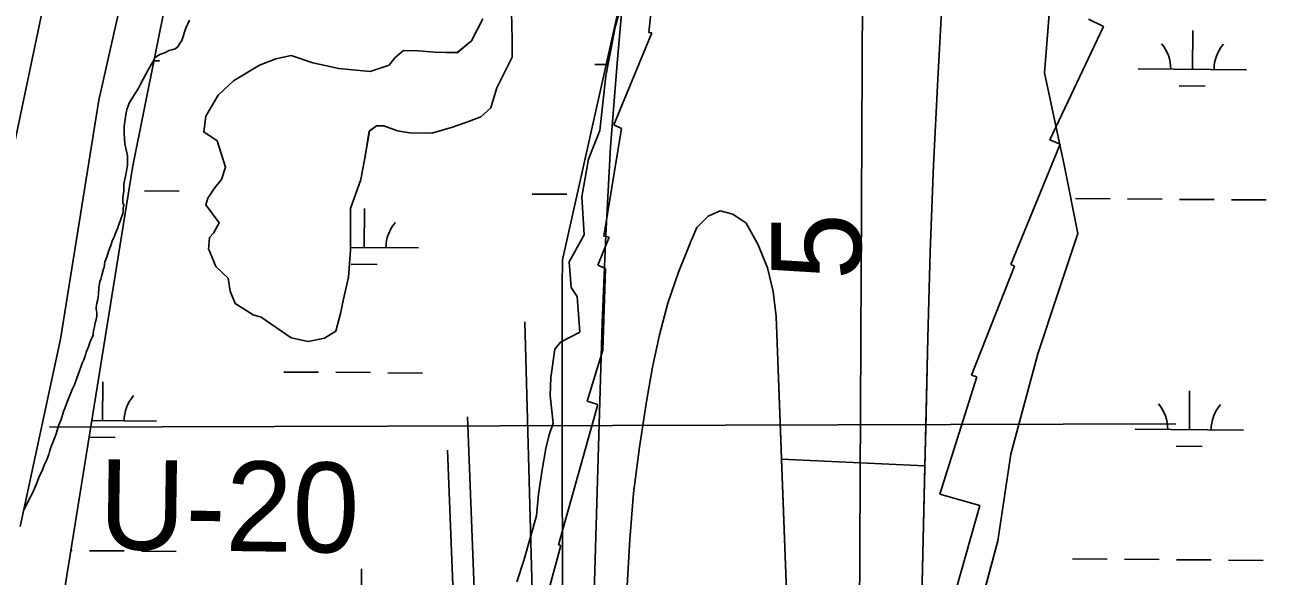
# Model space of a CAD drawing. Extents: x 3271442 to 3309282, y 752266 to 777610.
# Drawn here: x 3284369 to 3285515, y 760687 to 761196 of the extents above; entities that cross this region are included whole.
import ezdxf

# ---------------------------------------------------------------- set-up
doc = ezdxf.new("R2010")
doc.units = 0
for name, color, linetype in [('V-LEVE-TOET', 7, 'Continuous'), ('V-RIVR-RANG', 7, 'Continuous'), ('V-RIVR-RANG-IDEN', 7, 'Continuous'), ('V-RRAP-RVMT', 7, 'Continuous'), ('V-SITE-VEGE', 7, 'Continuous'), ('V-SURV-LINE', 7, 'Continuous'), ('V-TOPO-DPTH', 7, 'Continuous'), ('V-TOPO-MAJR', 7, 'Continuous'), ('V-TOPO-MINR', 7, 'Continuous'), ('V-TOPO-MINR-IDEN', 7, 'Continuous'), ('V-TOPO-SHOR', 7, 'Continuous'), ('V-TOPO-WATR', 7, 'Continuous'), ('V-WETL-SWMP', 7, 'Continuous')]:
    doc.layers.add(name, color=color, linetype=linetype)

msp = doc.modelspace()

# ---------------------------------------------------------------- linework, layer by layer
at = {"layer": 'V-LEVE-TOET'}
msp.add_lwpolyline([(3284364.4, 760732.6), (3284401.6, 760905.6), (3284437.2, 761126.1), (3284466.3, 761256), (3284536.5, 761573.6), (3284580.9, 761825.5), (3284684.3, 762338.7), (3284774.1, 762796.9), (3284845.7, 763187.2), (3284909.2, 763499.9), (3284968.8, 763777.1), (3284994.4, 763906.7), (3284995.4, 763964), (3285002.6, 764015), (3285013.5, 764062), (3285019.1, 764089.2)], dxfattribs=at)
at = {"layer": 'V-RIVR-RANG'}
msp.add_line((3284391.5, 760824.3), (3285431.5, 760827.4), dxfattribs=at)
at = {"layer": 'V-RRAP-RVMT'}
for p, q in [((3284945, 761188.5), (3284948.1, 761217.6)), ((3285364.8, 761194.1), (3285315.2, 761089.4)), ((3285350.9, 761200.9), (3285364.8, 761194.1)), ((3284912.7, 761103.4), (3284947.7, 761188.3)), ((3284947.7, 761188.3), (3284945, 761188.5)), ((3284903.4, 761000.5), (3284919.7, 761100)), ((3284919.7, 761100), (3284912.7, 761103.4)), ((3285315.2, 761089.4), (3285324.9, 761085.4)), ((3285324.9, 761085.4), (3285279.2, 760974.4)), ((3284897.9, 760973.7), (3284908.2, 760999.7)), ((3284908.2, 760999.7), (3284903.4, 761000.5)), ((3284905.1, 760970.9), (3284897.9, 760973.7)), ((3285282.7, 760973), (3285243, 760872.4)), ((3285279.2, 760974.4), (3285282.7, 760973)), ((3284902.6, 760895.5), (3284905.1, 760970.9)), ((3284887.9, 760848.3), (3284902.6, 760895.5)), ((3285248, 760870.8), (3285213.7, 760762.3)), ((3285243, 760872.4), (3285248, 760870.8)), ((3284897.8, 760845.1), (3284887.9, 760848.3)), ((3284861.4, 760715.6), (3284897.8, 760845.1)), ((3285213.7, 760762.3), (3285250.5, 760751.9)), ((3285250.5, 760751.9), (3285217, 760633.1)), ((3284844.3, 760643), (3284863.7, 760715)), ((3284863.7, 760715), (3284861.4, 760715.6))]:
    msp.add_line(p, q, dxfattribs=at)
at = {"layer": 'V-SITE-VEGE'}
for p, q in [((3284818.8, 761182.6), (3284818.1, 761207.2)), ((3284917.3, 761205.6), (3284914, 761193.4)), ((3284513.6, 761181.1), (3284517.3, 761192.5)), ((3284517.3, 761192.5), (3284520.9, 761200.1)), ((3284791.7, 761201.1), (3284781.3, 761180.9)), ((3284914, 761193.4), (3284905.3, 761148.7)), ((3284511.4, 761178.2), (3284513.6, 761181.1)), ((3284781.3, 761180.9), (3284768, 761170)), ((3284818.7, 761165.7), (3284818.8, 761182.6)), ((3284488.9, 761165.4), (3284493.4, 761168.3)), ((3284493.4, 761168.3), (3284498.5, 761170.2)), ((3284498.5, 761170.2), (3284501.8, 761172)), ((3284501.8, 761172), (3284504.4, 761172.7)), ((3284504.4, 761172.7), (3284507.7, 761173.4)), ((3284507.7, 761173.4), (3284509.9, 761175.3)), ((3284509.9, 761175.3), (3284511.4, 761178.2)), ((3284718.4, 761172), (3284710.3, 761165.1)), ((3284732, 761171.6), (3284718.4, 761172)), ((3284747.1, 761170.4), (3284732, 761171.6)), ((3284768, 761170), (3284747.1, 761170.4)), ((3284482.6, 761154.1), (3284487.7, 761163.2)), ((3284487.7, 761163.2), (3284488.9, 761165.4)), ((3284585.3, 761158.6), (3284561.4, 761144)), ((3284600.4, 761164.4), (3284585.3, 761158.6)), ((3284614.8, 761167.3), (3284600.4, 761164.4)), ((3284634.6, 761160.6), (3284614.8, 761167.3)), ((3284658.8, 761155.4), (3284634.6, 761160.6)), ((3284705.1, 761158.5), (3284687.5, 761152.7)), ((3284710.3, 761165.1), (3284705.1, 761158.5)), ((3284804.6, 761137.5), (3284818.7, 761165.7)), ((3284475.6, 761140.9), (3284482.6, 761154.1)), ((3284687.5, 761152.7), (3284658.8, 761155.4)), ((3284905.3, 761148.7), (3284899.6, 761098)), ((3284470, 761131.3), (3284473.4, 761136.5)), ((3284473.4, 761136.5), (3284475.6, 761140.9)), ((3284561.4, 761144), (3284547.4, 761130.9)), ((3284802.4, 761130.5), (3284804.6, 761137.5)), ((3284463, 761117.4), (3284465.2, 761123.3)), ((3284465.2, 761123.3), (3284470, 761131.3)), ((3284547.4, 761130.9), (3284535.9, 761111.5)), ((3284799, 761119.1), (3284802.4, 761130.5)), ((3284460.4, 761102), (3284462.2, 761114.5)), ((3284462.2, 761114.5), (3284463, 761117.4)), ((3284535.9, 761111.5), (3284534, 761096.8)), ((3284779.5, 761106.7), (3284789.8, 761110.7)), ((3284789.8, 761110.7), (3284799, 761119.1)), ((3284460.3, 761095.4), (3284460.4, 761102)), ((3284686.8, 761097.6), (3284693.5, 761102.3)), ((3284693.5, 761102.3), (3284700.1, 761102.6)), ((3284700.1, 761102.6), (3284712.9, 761097.8)), ((3284744.5, 761095.8), (3284763.7, 761101.3)), ((3284763.7, 761101.3), (3284779.5, 761106.7)), ((3284461, 761085.8), (3284460.3, 761095.4)), ((3284534, 761096.8), (3284546.4, 761088.6)), ((3284546.4, 761088.6), (3284554.1, 761064.3)), ((3284682.7, 761072.6), (3284686.8, 761097.6)), ((3284712.9, 761097.8), (3284724, 761095.9)), ((3284724, 761095.9), (3284744.5, 761095.8)), ((3284899.6, 761098), (3284889.2, 761071.6)), ((3284462.5, 761079.2), (3284461, 761085.8)), ((3284463.5, 761074.8), (3284462.5, 761079.2)), ((3284462.7, 761060.5), (3284463.5, 761066)), ((3284463.5, 761066), (3284463.5, 761074.8)), ((3284678.9, 761052.8), (3284682.7, 761072.6)), ((3284889.2, 761071.6), (3284883.2, 761037)), ((3284460.1, 761048.7), (3284462.7, 761060.5)), ((3284554.1, 761064.3), (3284550.3, 761053)), ((3284459.3, 761035.9), (3284460.1, 761042.5)), ((3284460.1, 761042.5), (3284460.1, 761048.7)), ((3284544, 761044.9), (3284537.8, 761035.8)), ((3284550.3, 761053), (3284544, 761044.9)), ((3284669.6, 761026), (3284678.9, 761052.8)), ((3284459.3, 761031.4), (3284459.3, 761035.9)), ((3284459.5, 761030.9), (3284459.3, 761031.4)), ((3284460, 761029.2), (3284459.5, 761030.9)), ((3284537.8, 761035.8), (3284535.9, 761029.5)), ((3284883.2, 761037), (3284885.2, 761001.8)), ((3284457.5, 761016.3), (3284458.3, 761019.2)), ((3284458.3, 761019.2), (3284459.2, 761021.3)), ((3284459.2, 761021.3), (3284459.6, 761024.2)), ((3284459.6, 761026.3), (3284460, 761029.2)), ((3284459.6, 761024.2), (3284459.6, 761026.3)), ((3284535.9, 761029.5), (3284548.3, 761012.9)), ((3284669.5, 760987.8), (3284669.6, 761026)), ((3284452.4, 761003.3), (3284454.5, 761008.3)), ((3284454.5, 761008.3), (3284455, 761009.8)), ((3284455, 761009.8), (3284455.4, 761011.2)), ((3284455.4, 761011.2), (3284457.5, 761016.3)), ((3284548.3, 761012.9), (3284542.8, 761003.4)), ((3284448.2, 760992), (3284449.5, 760996.1)), ((3284449.5, 760996.1), (3284450.3, 760998.2)), ((3284450.3, 760998.2), (3284451.6, 761000.7)), ((3284451.6, 761000.7), (3284452.4, 761003.3)), ((3284539.4, 760999.4), (3284538.3, 760988.3)), ((3284542.8, 761003.4), (3284539.4, 760999.4)), ((3284885.2, 761001.8), (3284871.5, 760976.8)), ((3284444.4, 760981.1), (3284446.1, 760986.5)), ((3284446.1, 760986.5), (3284447, 760989)), ((3284447, 760989), (3284448.2, 760992)), ((3284538.3, 760988.3), (3284539, 760987.6)), ((3284539, 760987.6), (3284545.2, 760972.5)), ((3284667.5, 760962.8), (3284669.5, 760987.8)), ((3284441.9, 760971.8), (3284442.7, 760976.9)), ((3284442.7, 760976.9), (3284444.4, 760981.1)), ((3284871.5, 760976.8), (3284873.2, 760953.3)), ((3284438.9, 760960.9), (3284439.8, 760964.7)), ((3284439.8, 760964.7), (3284441.5, 760970.5)), ((3284441.5, 760970.5), (3284441.9, 760971.8)), ((3284545.2, 760972.5), (3284556.5, 760961.8)), ((3284556.5, 760961.8), (3284558.3, 760949.7)), ((3284662.6, 760941.1), (3284667.5, 760962.8)), ((3284436.8, 760947.1), (3284437.2, 760953)), ((3284437.2, 760953), (3284438.1, 760958.9)), ((3284438.1, 760958.9), (3284438.9, 760960.9)), ((3284873.2, 760953.3), (3284878.7, 760944.8)), ((3284434.7, 760935), (3284435.1, 760938.7)), ((3284435.1, 760938.7), (3284436, 760942.1)), ((3284436, 760942.1), (3284436.8, 760947.1)), ((3284558.3, 760949.7), (3284563, 760938.3)), ((3284660.4, 760930.5), (3284662.6, 760941.1)), ((3284878.7, 760944.8), (3284881.1, 760912.1)), ((3284434.7, 760932.9), (3284434.7, 760935)), ((3284435.1, 760930.4), (3284434.7, 760932.9)), ((3284435.1, 760926.6), (3284435.1, 760930.4)), ((3284563, 760938.3), (3284579.5, 760927.9)), ((3284579.5, 760927.9), (3284586.9, 760925.7)), ((3284655.9, 760912.9), (3284660.4, 760930.5)), ((3284432.1, 760913.2), (3284433, 760916.9)), ((3284433, 760916.9), (3284433.8, 760920.7)), ((3284433.8, 760920.7), (3284434.7, 760923.6)), ((3284434.7, 760923.6), (3284435.1, 760926.6)), ((3284586.9, 760925.7), (3284614.7, 760906.8)), ((3284428.8, 760902.3), (3284430.5, 760906.9)), ((3284430.5, 760906.9), (3284431.7, 760909)), ((3284431.7, 760910.7), (3284432.1, 760913.2)), ((3284431.7, 760909), (3284431.7, 760910.7)), ((3284614.7, 760906.8), (3284630.5, 760903.4)), ((3284630.5, 760903.4), (3284645.6, 760906.3)), ((3284645.6, 760906.3), (3284655.9, 760912.9)), ((3284881.1, 760912.1), (3284863.4, 760902.6)), ((3284424.6, 760891), (3284425.4, 760893.5)), ((3284425.4, 760893.5), (3284427.5, 760898.5)), ((3284427.5, 760898.5), (3284428.8, 760902.3)), ((3284858.3, 760896.4), (3284854.5, 760870)), ((3284863.4, 760902.6), (3284858.3, 760896.4)), ((3284420.8, 760880.5), (3284421.6, 760883.4)), ((3284421.6, 760883.4), (3284423.3, 760886.4)), ((3284423.3, 760886.4), (3284424.6, 760891)), ((3284414.5, 760863.3), (3284416.6, 760869.6)), ((3284416.6, 760869.6), (3284419.1, 760876.3)), ((3284419.1, 760876.3), (3284420.8, 760880.5)), ((3284854.5, 760870), (3284853.7, 760853.5)), ((3284408.1, 760848.2), (3284412.3, 760859.1)), ((3284412.3, 760859.1), (3284414.5, 760863.3)), ((3284406, 760842.4), (3284408.1, 760848.2)), ((3284853.7, 760853.5), (3284856.5, 760828.1)), ((3284402.2, 760831.5), (3284404.4, 760838.6)), ((3284404.4, 760838.6), (3284406, 760842.4)), ((3284397.6, 760818.1), (3284400.1, 760826.5)), ((3284400.1, 760826.5), (3284402.2, 760831.5)), ((3284856.5, 760828.1), (3284852.8, 760817.1)), ((3284395.1, 760811.8), (3284397.6, 760818.1)), ((3284852.8, 760817.1), (3284849.8, 760804.6)), ((3284390.9, 760799.2), (3284391.7, 760802.6)), ((3284391.7, 760802.6), (3284393, 760806.3)), ((3284393, 760806.3), (3284395.1, 760811.8)), ((3284849.8, 760804.6), (3284846.4, 760784.8)), ((3284386.7, 760789.2), (3284388.8, 760793.4)), ((3284388.8, 760793.4), (3284390.9, 760799.2)), ((3284381.6, 760777.9), (3284385, 760785)), ((3284385, 760785), (3284386.7, 760789.2)), ((3284846.4, 760784.8), (3284843, 760762.4)), ((3284375.7, 760763.2), (3284379.5, 760772)), ((3284379.5, 760772), (3284381.6, 760777.9)), ((3284367.7, 760747.7), (3284372.3, 760757.3)), ((3284372.3, 760757.3), (3284375.7, 760763.2)), ((3284843, 760762.4), (3284841.1, 760742.5)), ((3284841.1, 760742.5), (3284829.5, 760701.1)), ((3284829.5, 760701.1), (3284823.1, 760681.6))]:
    msp.add_line(p, q, dxfattribs=at)
msp.add_lwpolyline([(3285242.4, 760626.6), (3285267.1, 760719.2), (3285279.4, 760799.5), (3285304.1, 760892), (3285322.6, 760947.6), (3285341.1, 761003.2), (3285328.8, 761064.9), (3285310.2, 761151.3), (3285317.4, 761240.3)], dxfattribs=at)
at = {"layer": 'V-SURV-LINE'}
msp.add_lwpolyline([(3284456.7, 761551.7), (3284311.1, 760858.6)], dxfattribs=at)
at = {"layer": 'V-TOPO-DPTH'}
for points in [[(3285248.1, 762689.8), (3284865.2, 760978.9)], [(3285066.9, 760812.8), (3285067.6, 760794.8), (3285199.9, 760788.7), (3285200.7, 760823), (3285202.6, 760906.7), (3285204.9, 760986.3), (3285207.8, 761066), (3285211.7, 761145.6), (3285216.2, 761225.2)], [(3285074, 760623.7), (3285062.7, 760926.5), (3285059.9, 760949.4), (3285054.7, 760971.5), (3285045.9, 760992.5), (3285034.7, 761012.7), (3285022.5, 761021), (3285010.8, 761024), (3284999.8, 761019), (3284989.3, 761008.7), (3284983.6, 760995.8), (3284972.4, 760967.5), (3284962.5, 760938.8), (3284954.7, 760909.4), (3284948.3, 760879.6), (3284942.8, 760848.1), (3284936.3, 760805.7), (3284930.9, 760763.3), (3284927.3, 760720.6), (3284924.9, 760677.9)], [(3284924.9, 760677.9), (3284927.3, 760720.6), (3284930.9, 760763.3), (3284936.3, 760805.7), (3284942.8, 760848.1), (3284948.3, 760879.6), (3284954.7, 760909.4), (3284962.5, 760938.8), (3284972.4, 760967.5), (3284983.6, 760995.8), (3284989.3, 761008.7), (3284999.8, 761019), (3285010.8, 761024), (3285022.5, 761021), (3285034.7, 761012.7), (3285045.9, 760992.5), (3285054.7, 760971.5), (3285059.9, 760949.4), (3285062.7, 760926.5), (3285066.9, 760812.8)], [(3284865.2, 760978.9), (3284865, 760954.7), (3284864.9, 760863.3), (3284865.1, 760619.4)], [(3285067.6, 760794.8), (3285074, 760623.7), (3285074.3, 760605.8), (3285074, 760587.8), (3285072.9, 760569.9), (3285071.4, 760552), (3285052.3, 760380.3), (3285049.2, 760362), (3285044.8, 760344), (3285038.3, 760326.6), (3285030.5, 760309.6), (3285020.5, 760299.9), (3285009.7, 760294.6), (3284997.8, 760296), (3284985.1, 760301.8), (3284980.7, 760305.8), (3284966.3, 760321.5), (3284954, 760338.4), (3284944.7, 760357.2), (3284937.5, 760377.3), (3284936.9, 760379.7), (3284931.9, 760402.1), (3284927.9, 760424.7)], [(3285196.6, 760640.4), (3285199.9, 760788.7), (3285067.6, 760794.8)]]:
    msp.add_lwpolyline(points, dxfattribs=at)
at = {"layer": 'V-TOPO-MAJR'}
msp.add_lwpolyline([(3284759.1, 760803.1), (3284766, 760624)], dxfattribs=at)
at = {"layer": 'V-TOPO-MINR'}
for points in [[(3285085.1, 762295.5), (3285005.9, 761797.5), (3284995.4, 761732.3), (3284984.6, 761667.1), (3284973.6, 761602), (3284962.3, 761536.9), (3284947.4, 761451.6), (3284943.7, 761429.1), (3284940.3, 761406.6), (3284937.4, 761384), (3284934.9, 761361.4), (3284923.2, 761244.9), (3284915.9, 761164), (3284909.7, 761083), (3284905.3, 761001.8), (3284902, 760920.6), (3284893.7, 760640)], [(3285196.6, 760640.4), (3285202.6, 760906.7), (3285204.9, 760986.3), (3285207.8, 761066), (3285211.7, 761145.6), (3285216.2, 761225.2), (3285222.6, 761326.5), (3285225, 761355.3), (3285228.2, 761384), (3285232.7, 761412.6), (3285238, 761441), (3285265.7, 761574.1), (3285275.3, 761617.5), (3285285.6, 761660.6), (3285297.1, 761703.5), (3285309.3, 761746.2), (3285316, 761768.6), (3285325.7, 761799.8), (3285336.1, 761830.8), (3285347.2, 761861.6), (3285358.8, 761892.1), (3285370.2, 761922.7), (3285380.7, 761953.6)], [(3285139.3, 760586), (3285142.8, 761349.4), (3285143.2, 761370.1), (3285144.1, 761390.7), (3285145.6, 761411.4), (3285147.6, 761431.9), (3285170.6, 761637.5), (3285179, 761698.4), (3285189.4, 761759), (3285202.9, 761819), (3285218.5, 761878.6), (3285237.9, 761945.7)], [(3284865.2, 760978.9), (3284865, 760954.7), (3284864.9, 760863.3), (3284865.1, 760619.4)], [(3284830.4, 760921.4), (3284839.4, 760594.4)], [(3284777.6, 760833.8), (3284784.9, 760643.2)]]:
    msp.add_lwpolyline(points, dxfattribs=at)
at = {"layer": 'V-TOPO-SHOR'}
for points in [[(3284818.1, 761207.2), (3284818.8, 761182.6), (3284818.7, 761165.7), (3284804.6, 761137.5), (3284802.4, 761130.5), (3284799, 761119.1), (3284789.8, 761110.7), (3284779.5, 761106.7), (3284763.7, 761101.3), (3284744.5, 761095.8), (3284724, 761095.9), (3284712.9, 761097.8), (3284700.1, 761102.6), (3284693.5, 761102.3), (3284686.8, 761097.6), (3284682.7, 761072.6), (3284678.9, 761052.8), (3284669.6, 761026), (3284669.5, 761002.5), (3284669.5, 760987.8), (3284667.5, 760962.8), (3284662.6, 760941.1), (3284660.4, 760930.5), (3284655.9, 760912.9)], [(3284917.3, 761205.6), (3284914, 761193.4), (3284910.2, 761174), (3284905.3, 761148.7), (3284899.6, 761098), (3284889.2, 761071.6), (3284883.2, 761037), (3284885.2, 761001.8), (3284871.5, 760976.8), (3284873.2, 760953.3), (3284878.7, 760944.8), (3284881.1, 760912.1), (3284863.4, 760902.6), (3284858.3, 760896.4), (3284854.5, 760870), (3284853.7, 760853.5), (3284856.5, 760828.1), (3284852.8, 760817.1), (3284849.8, 760804.6), (3284846.4, 760784.8), (3284843, 760762.4), (3284841.1, 760742.5), (3284829.5, 760701.1), (3284823.1, 760681.6)], [(3284538.3, 760988.3), (3284539.4, 760999.4), (3284542.8, 761003.4), (3284548.3, 761012.9), (3284535.9, 761029.5), (3284537.8, 761035.8), (3284544, 761044.9), (3284550.3, 761053), (3284554.1, 761064.3), (3284546.4, 761088.6), (3284534, 761096.8), (3284535.9, 761111.5), (3284547.4, 761130.9), (3284561.4, 761144), (3284585.3, 761158.6), (3284600.4, 761164.4), (3284614.8, 761167.3), (3284634.6, 761160.6), (3284658.8, 761155.4), (3284687.5, 761152.7), (3284705.1, 761158.5), (3284710.3, 761165.1), (3284718.4, 761172), (3284732, 761171.6), (3284747.1, 761170.4), (3284768, 761169.9), (3284781.3, 761180.9), (3284791.7, 761201.1)], [(3284655.9, 760912.9), (3284645.6, 760906.3), (3284630.5, 760903.4), (3284614.7, 760906.8), (3284586.9, 760925.7), (3284579.5, 760927.9), (3284563, 760938.3), (3284558.3, 760949.7), (3284556.5, 760961.8), (3284545.2, 760972.5), (3284539, 760987.6), (3284538.3, 760988.3)]]:
    msp.add_lwpolyline(points, dxfattribs=at)
at = {"layer": 'V-TOPO-WATR'}
msp.add_lwpolyline([(3285074, 760623.7), (3285062.7, 760926.5), (3285059.9, 760949.4), (3285054.7, 760971.5), (3285045.9, 760992.5), (3285034.7, 761012.7), (3285022.5, 761021), (3285010.8, 761024), (3284999.8, 761019), (3284989.3, 761008.7), (3284983.6, 760995.8), (3284972.4, 760967.5), (3284962.5, 760938.8), (3284954.7, 760909.4), (3284948.3, 760879.6), (3284942.8, 760848.1), (3284936.3, 760805.7), (3284930.9, 760763.3), (3284927.3, 760720.6), (3284924.9, 760677.9)], dxfattribs=at)
at = {"layer": 'V-WETL-SWMP'}
for p, q in [((3284468.5, 761065.5), (3284951.3, 763462.5)), ((3285310.2, 761151.3), (3285318.1, 761248.6)), ((3284818.8, 761182.6), (3284818.2, 761207.2)), ((3284917.3, 761205.6), (3284914, 761193.4)), ((3284791.7, 761201.1), (3284781.3, 761180.9)), ((3284914, 761193.4), (3284905.3, 761148.7)), ((3285446.9, 761154.6), (3285447.2, 761190.6)), ((3284781.3, 761180.9), (3284768, 761169.9)), ((3284818.7, 761165.7), (3284818.8, 761182.6)), ((3284718.4, 761172), (3284710.3, 761165.1)), ((3284732, 761171.6), (3284718.4, 761172)), ((3284747.1, 761170.4), (3284732, 761171.6)), ((3284768, 761169.9), (3284747.1, 761170.4)), ((3284488, 761162.5), (3284493.1, 761162.4)), ((3284585.3, 761158.6), (3284561.4, 761144)), ((3284600.4, 761164.4), (3284585.3, 761158.6)), ((3284614.8, 761167.3), (3284600.4, 761164.4)), ((3284634.6, 761160.6), (3284614.8, 761167.3)), ((3284658.8, 761155.4), (3284634.6, 761160.6)), ((3284705.1, 761158.5), (3284687.5, 761152.7)), ((3284710.3, 761165.1), (3284705.1, 761158.5)), ((3284804.6, 761137.5), (3284818.7, 761165.7)), ((3284895, 761159.1), (3284907.3, 761159)), ((3284687.5, 761152.7), (3284658.8, 761155.4)), ((3284905.3, 761148.7), (3284899.6, 761098)), ((3285328.8, 761064.9), (3285310.2, 761151.3)), ((3285396.9, 761155), (3285496.9, 761154.2)), ((3284561.4, 761144), (3284547.4, 761130.9)), ((3284802.4, 761130.5), (3284804.6, 761137.5)), ((3285434.8, 761139.3), (3285458.8, 761139.1)), ((3284547.4, 761130.9), (3284535.9, 761111.5)), ((3284799, 761119.1), (3284802.4, 761130.5)), ((3284535.9, 761111.5), (3284534, 761096.8)), ((3284779.5, 761106.7), (3284789.8, 761110.7)), ((3284789.8, 761110.7), (3284799, 761119.1)), ((3284686.9, 761097.6), (3284693.5, 761102.3)), ((3284693.5, 761102.3), (3284700.1, 761102.6)), ((3284700.1, 761102.6), (3284712.9, 761097.8)), ((3284744.5, 761095.8), (3284763.7, 761101.3)), ((3284763.7, 761101.3), (3284779.5, 761106.7)), ((3284534, 761096.8), (3284546.4, 761088.6)), ((3284546.4, 761088.6), (3284554.1, 761064.3)), ((3284682.7, 761072.6), (3284686.9, 761097.6)), ((3284712.9, 761097.8), (3284724, 761095.9)), ((3284724, 761095.9), (3284744.5, 761095.8)), ((3284899.6, 761098), (3284889.2, 761071.6)), ((3284222.4, 759540.2), (3284468.5, 761065.5)), ((3284678.9, 761052.8), (3284682.7, 761072.6)), ((3284889.2, 761071.6), (3284883.2, 761037)), ((3285341.1, 761003.2), (3285328.8, 761064.9)), ((3284554.1, 761064.3), (3284550.3, 761053)), ((3284479.3, 761042.5), (3284511.3, 761042.2)), ((3284544, 761044.9), (3284537.8, 761035.8)), ((3284550.3, 761053), (3284544, 761044.9)), ((3284669.6, 761026), (3284678.9, 761052.8)), ((3284537.8, 761035.8), (3284535.9, 761029.5)), ((3284837.2, 761039.5), (3284869.2, 761039.3)), ((3284883.2, 761037), (3284885.2, 761001.8)), ((3285339.1, 761035.4), (3285371.1, 761035.1)), ((3285387.1, 761035), (3285419.1, 761034.7)), ((3285435.1, 761034.6), (3285467.1, 761034.3)), ((3285483.1, 761034.2), (3285515.1, 761034)), ((3284535.9, 761029.5), (3284548.3, 761012.9)), ((3284669.5, 760987.8), (3284669.6, 761026)), ((3284682.2, 760990.1), (3284682.5, 761026.1)), ((3284548.3, 761012.9), (3284542.8, 761003.4)), ((3284539.4, 760999.4), (3284538.3, 760988.3)), ((3284542.8, 761003.4), (3284539.4, 760999.4)), ((3284885.2, 761001.8), (3284871.5, 760976.8)), ((3285322.6, 760947.6), (3285341.1, 761003.2)), ((3284538.3, 760988.3), (3284539, 760987.6)), ((3284539, 760987.6), (3284545.2, 760972.5)), ((3284667.5, 760962.8), (3284669.5, 760987.8)), ((3284669.5, 760990.2), (3284732.2, 760989.7)), ((3284670, 760974.7), (3284694, 760974.5)), ((3284871.5, 760976.8), (3284873.2, 760953.3)), ((3284545.2, 760972.5), (3284556.5, 760961.8)), ((3284556.5, 760961.8), (3284558.3, 760949.7)), ((3284662.6, 760941.1), (3284667.5, 760962.8)), ((3284873.2, 760953.3), (3284878.7, 760944.8)), ((3284558.3, 760949.7), (3284563, 760938.3)), ((3284660.4, 760930.5), (3284662.6, 760941.1)), ((3284878.7, 760944.8), (3284881.1, 760912.1)), ((3285304.1, 760892.1), (3285322.6, 760947.6)), ((3284563, 760938.3), (3284579.5, 760927.9)), ((3284579.5, 760927.9), (3284586.9, 760925.7)), ((3284655.9, 760912.9), (3284660.4, 760930.5)), ((3284586.9, 760925.7), (3284614.7, 760906.8)), ((3284614.7, 760906.8), (3284630.5, 760903.4)), ((3284630.5, 760903.4), (3284645.6, 760906.3)), ((3284645.6, 760906.3), (3284655.9, 760912.9)), ((3284881.1, 760912.1), (3284863.4, 760902.6)), ((3284858.3, 760896.4), (3284854.5, 760870)), ((3284863.4, 760902.6), (3284858.3, 760896.4)), ((3285279.4, 760799.5), (3285304.1, 760892.1)), ((3284607.8, 760875.2), (3284639.8, 760875)), ((3284655.8, 760874.9), (3284687.8, 760874.6)), ((3284703.8, 760874.5), (3284735.8, 760874.2)), ((3284854.5, 760870), (3284853.7, 760853.5)), ((3284440.4, 760830.2), (3284440.7, 760866.2)), ((3284853.7, 760853.5), (3284856.5, 760828.1)), ((3285444.1, 760821.9), (3285444.4, 760857.9)), ((3284430.5, 760830.3), (3284490.4, 760829.8)), ((3284856.5, 760828.1), (3284852.8, 760817.1)), ((3284428.2, 760814.9), (3284452.2, 760814.7)), ((3284852.8, 760817.1), (3284849.8, 760804.6)), ((3285394.2, 760822.3), (3285494.1, 760821.5)), ((3284849.8, 760804.6), (3284846.4, 760784.8)), ((3285432, 760806.6), (3285456, 760806.4)), ((3285267.1, 760719.2), (3285279.4, 760799.5)), ((3284846.4, 760784.8), (3284843, 760762.4)), ((3284843, 760762.4), (3284841.1, 760742.5)), ((3284841.1, 760742.5), (3284829.5, 760701.1)), ((3284411.2, 760710.4), (3284412.5, 760710.3)), ((3284428.5, 760710.2), (3284460.5, 760710)), ((3284476.5, 760709.8), (3284508.5, 760709.6)), ((3285242.4, 760626.6), (3285267.1, 760719.2)), ((3284829.5, 760701.1), (3284823.1, 760681.6)), ((3285336.3, 760702.7), (3285368.3, 760702.5)), ((3285384.3, 760702.3), (3285416.3, 760702.1)), ((3285432.3, 760701.9), (3285464.3, 760701.7)), ((3285480.3, 760701.6), (3285512.3, 760701.3)), ((3284679.4, 760657.4), (3284679.7, 760693.4))]:
    msp.add_line(p, q, dxfattribs=at)
for centre, start, end in [((3285391.7, 761155.5), 358.7563, 40.2999), ((3285502.1, 761154.6), 138.7563, 180.2999), ((3284737.4, 760990.1), 138.7563, 180.2999), ((3284495.6, 760830.2), 138.7563, 180.2999), ((3285388.9, 760822.9), 358.7563, 40.2999), ((3285499.4, 760821.9), 138.7563, 180.2999)]:
    msp.add_arc(centre, 35.2, start, end, dxfattribs=at)

# ---------------------------------------------------------------- texts
at = {"layer": 'V-RIVR-RANG-IDEN'}
msp.add_text('U-20', height=83, rotation=359.1856, dxfattribs=at).set_placement((3284436.5, 760711.7))
at = {"layer": 'V-TOPO-MINR-IDEN'}
msp.add_text('5', height=83, rotation=89.7372, dxfattribs=at).set_placement((3285140.9, 760960))

doc.saveas('drawing.dxf')
